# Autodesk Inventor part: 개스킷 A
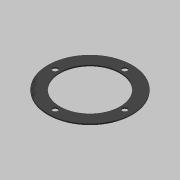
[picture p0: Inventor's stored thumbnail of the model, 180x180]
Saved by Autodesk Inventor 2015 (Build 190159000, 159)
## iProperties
Created: 2019-02
Part Number: 개스킷 A
Material: 고무
Document SubType Name: Modeling
Designer: mduedu
Density: 1 g/cm^3
Appearance: 고무 - 검은색 - 버전 1.1
Author: mduedu
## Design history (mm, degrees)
sketch "스케치1"
  geometry: C1 r 35 at (0, 0); C2 r 25 at (0, 0); 1 further point
  constraints: 2 centre point, 2 coincident
  dimensions: "d0" = 70 diameter of C1; "d1" = 50 diameter of C2
extrude "돌출1" new body sketch "스케치1" distance "d2" = 1; taper "d3" = 0 deg
sketch "스케치2" dims "d4" = 58
  geometry: 3 further points
  constraints: 2 vertical alignment, 1 coincident, 2 other
hole "구멍1" sketch "스케치2" at (0, 29) diameter "d5" = 4.5; stored, may be unused: countersink angle "d9" = 90 deg, drill point angle "d11" = 118 deg; dims "d6" = 6, "d7" = 4, "d8" = 2, "d10" = 8
node "솔리드1"
pattern_circular "원형 패턴1" dims angle "d13" = 360 deg
